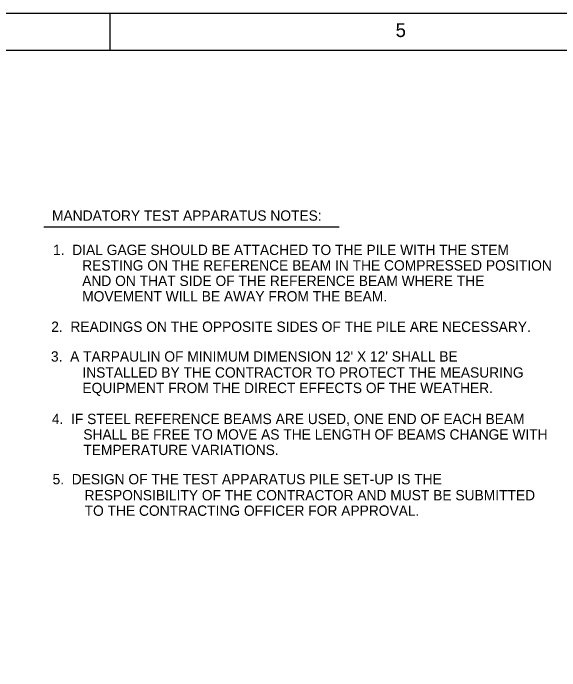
# Model space of a CAD drawing. Extents: x 22369.6 to 22413.6, y 22369.6 to 22403.6.
# Drawn here: x 22401.19 to 22408.62, y 22394.7 to 22403.63 of the extents above; entities that cross this region are included whole.
import ezdxf

# ---------------------------------------------------------------- set-up
doc = ezdxf.new("R2010")
doc.units = 0
for name, color, linetype in [('Level 1', 7, 'Continuous'), ('Level 10', 7, 'Continuous'), ('Level 4', 7, 'Continuous'), ('Level 7', 7, 'Continuous'), ('Level 9', 7, 'Continuous')]:
    doc.layers.add(name, color=color, linetype=linetype)

msp = doc.modelspace()

# ---------------------------------------------------------------- linework, layer by layer
at = {"layer": 'Level 1'}
msp.add_lwpolyline([(22369.6213, 22403.6293), (22413.6217, 22403.6293), (22413.6217, 22369.6213), (22369.6213, 22369.6213)], close=True, dxfattribs=at)
at = {"layer": 'Level 10'}
msp.add_line((22402.5097, 22403.1253), (22402.5097, 22403.6293), dxfattribs=at)
at = {"layer": 'Level 7'}
msp.add_line((22401.6109, 22400.7294), (22405.6178, 22400.7294), dxfattribs=at)
at = {"layer": 'Level 9'}
msp.add_line((22371.1213, 22403.1253), (22410.3697, 22403.1253), dxfattribs=at)

# ---------------------------------------------------------------- texts
at = {"layer": 'Level 1'}
msp.add_text('5', height=0.1873, dxfattribs=at).set_placement((22406.3857, 22403.3053))
at = {"layer": 'Level 4'}
for s, p in [('MANDATORY TEST APPARATUS NOTES:', (22401.7198, 22400.8123)), ('1.  DIAL GAGE SHOULD BE ATTACHED TO THE PILE WITH THE STEM', (22401.7343, 22400.3467)), ('RESTING ON THE REFERENCE BEAM IN THE COMPRESSED POSITION', (22402.1298, 22400.1367)), ('AND ON THAT SIDE OF THE REFERENCE BEAM WHERE THE', (22402.1298, 22399.9267)), ('MOVEMENT WILL BE AWAY FROM THE BEAM.', (22402.1298, 22399.7167)), ('2.  READINGS ON THE OPPOSITE SIDES OF THE PILE ARE NECESSARY.', (22401.7092, 22399.3039)), ("3.  A TARPAULIN OF MINIMUM DIMENSION 12' X 12' SHALL BE", (22401.7054, 22398.9006)), ('INSTALLED BY THE CONTRACTOR TO PROTECT THE MEASURING', (22402.1326, 22398.6831)), ('EQUIPMENT FROM THE DIRECT EFFECTS OF THE WEATHER.', (22402.1326, 22398.4731)), ('4.  IF STEEL REFERENCE BEAMS ARE USED, ONE END OF EACH BEAM', (22401.7181, 22398.0524)), ('SHALL BE FREE TO MOVE AS THE LENGTH OF BEAMS CHANGE WITH', (22402.1452, 22397.8424)), ('TEMPERATURE VARIATIONS.', (22402.1452, 22397.6324)), ('5.  DESIGN OF THE TEST APPARATUS PILE SET-UP IS THE ', (22401.7276, 22397.235)), ('RESPONSIBILITY OF THE CONTRACTOR AND MUST BE SUBMITTED', (22402.1626, 22397.0175)), ('TO THE CONTRACTING OFFICER FOR APPROVAL.', (22402.1626, 22396.8075))]:
    msp.add_text(s, height=0.14, dxfattribs=at).set_placement(p)

doc.saveas('drawing.dxf')
